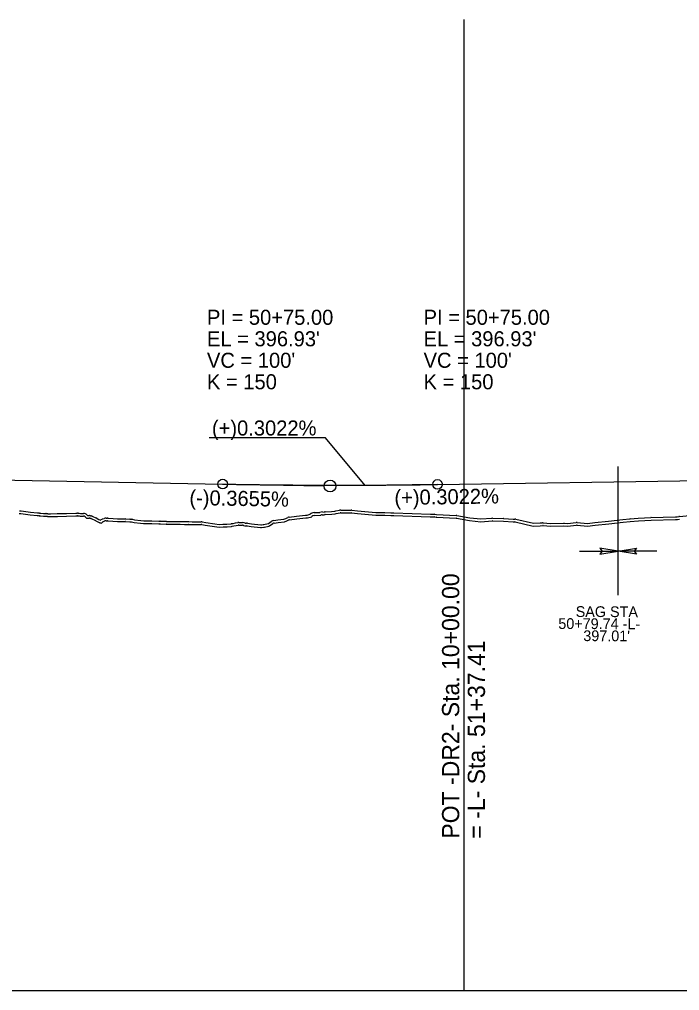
# Model space of a CAD drawing. Extents: x 1625686 to 1640492, y 1161393 to 1175642.
# Drawn here: x 1639842.2 to 1640149.4, y 1174910.8 to 1175362.5 of the extents above; entities that cross this region are included whole.
import ezdxf

# ---------------------------------------------------------------- set-up
doc = ezdxf.new("R2010")
doc.units = 0
for name, color, linetype in [('Exist Profile Cell', 7, 'Continuous'), ('Prop PFL Text', 7, 'Continuous'), ('Prop Plan Preparation Sag', 7, 'Continuous'), ('Prop Vertical Profile Curve Label', 7, 'Continuous'), ('Prop Vertical Profile Grade', 7, 'Continuous'), ('Prop Vertical Profile Grade Label', 7, 'Continuous'), ('Prop VPI Label', 7, 'Continuous'), ('Scratch_Level_1', 7, 'Continuous'), ('Scratch_Level_3', 7, 'Continuous')]:
    doc.layers.add(name, color=color, linetype=linetype)

msp = doc.modelspace()

# ---------------------------------------------------------------- linework, layer by layer
at = {"layer": 'Exist Profile Cell'}
msp.add_line((1635911.78, 1174910.79), (1640378.1, 1174910.79), dxfattribs=at)
at = {"layer": 'Prop PFL Text'}
msp.add_line((1640049.19, 1174977.9), (1640049.19, 1175146.38), dxfattribs=at)
at = {"layer": 'Prop Plan Preparation Sag'}
for p, q in [((1640120.85, 1175094.7), (1640120.85, 1175154.46)), ((1640102.85, 1175115.13), (1640120.85, 1175115.13)), ((1640138.85, 1175115.13), (1640120.85, 1175115.13))]:
    msp.add_line(p, q, dxfattribs=at)
for points in [[(1640112.29, 1175113.71), (1640120.85, 1175115.13), (1640112.29, 1175116.56), (1640113.35, 1175115.13)], [(1640129.42, 1175113.71), (1640120.85, 1175115.13), (1640129.42, 1175116.56), (1640128.35, 1175115.13)]]:
    msp.add_lwpolyline(points, close=True, dxfattribs=at)
at = {"layer": 'Prop Vertical Profile Curve Label'}
for centre in [(1639936.78, 1175146.35), (1640036.78, 1175146.19)]:
    msp.add_circle(centre, 2.25, dxfattribs=at)
at = {"layer": 'Prop Vertical Profile Grade'}
for p, q in [((1639521.78, 1175153.93), (1639936.78, 1175146.35)), ((1640036.78, 1175146.19), (1640211.78, 1175148.84))]:
    msp.add_line(p, q, dxfattribs=at)
msp.add_spline([(1639936.78, 1175146.35), (1639938.78, 1175146.31), (1639940.78, 1175146.28), (1639942.78, 1175146.25), (1639944.78, 1175146.21), (1639946.78, 1175146.18), (1639948.78, 1175146.15), (1639950.78, 1175146.13), (1639952.78, 1175146.1), (1639954.78, 1175146.08), (1639956.78, 1175146.05), (1639958.78, 1175146.03), (1639960.78, 1175146.01), (1639962.78, 1175145.99), (1639964.78, 1175145.97), (1639966.78, 1175145.95), (1639968.78, 1175145.94), (1639970.78, 1175145.92), (1639972.78, 1175145.91), (1639974.78, 1175145.9), (1639976.78, 1175145.89), (1639978.78, 1175145.88), (1639980.78, 1175145.87), (1639982.78, 1175145.86), (1639984.78, 1175145.86), (1639986.78, 1175145.85), (1639988.78, 1175145.85), (1639990.78, 1175145.85), (1639992.78, 1175145.85), (1639994.78, 1175145.85), (1639996.78, 1175145.85), (1639998.78, 1175145.86), (1640000.78, 1175145.86), (1640002.78, 1175145.87), (1640004.78, 1175145.88), (1640006.78, 1175145.89), (1640008.78, 1175145.9), (1640010.78, 1175145.91), (1640012.78, 1175145.93), (1640014.78, 1175145.94), (1640016.78, 1175145.96), (1640018.78, 1175145.97), (1640020.78, 1175145.99), (1640022.78, 1175146.01), (1640024.78, 1175146.03), (1640026.78, 1175146.06), (1640028.78, 1175146.08), (1640030.78, 1175146.11), (1640032.78, 1175146.13), (1640034.78, 1175146.16), (1640036.78, 1175146.19)], degree=3, dxfattribs=at)
at = {"layer": 'Prop Vertical Profile Grade Label'}
for p, q in [((1639984.65, 1175167.83), (1639930.45, 1175167.83)), ((1640003.16, 1175145.68), (1639984.65, 1175167.83))]:
    msp.add_line(p, q, dxfattribs=at)
at = {"layer": 'Prop VPI Label'}
for p, q in [((1639936.78, 1175146.35), (1639984.03, 1175145.49)), ((1640036.78, 1175146.19), (1639989.53, 1175145.48))]:
    msp.add_line(p, q, dxfattribs=at)
msp.add_circle((1639986.78, 1175145.44), 2.75, dxfattribs=at)
at = {"layer": 'Scratch_Level_1'}
for p, q in [((1639854.61, 1175132.65), (1639855.24, 1175132.6)), ((1639979.31, 1175133.07), (1639982.05, 1175133.15)), ((1640035.36, 1175132.31), (1640036.28, 1175132.26)), ((1640036.31, 1175132.26), (1640045.53, 1175131.7)), ((1640149.32, 1175131.33), (1640157.05, 1175132.05)), ((1639854.53, 1175131.4), (1639855.16, 1175131.36)), ((1639875.01, 1175130.44), (1639875.34, 1175130.36)), ((1639875.29, 1175131.65), (1639875.63, 1175131.58)), ((1639875.58, 1175130.28), (1639877.63, 1175129.35)), ((1639876.09, 1175131.42), (1639878.14, 1175130.49)), ((1639880.89, 1175130.13), (1639881.57, 1175130.39)), ((1639881.34, 1175128.96), (1639882.02, 1175129.23)), ((1639882.52, 1175129.31), (1639883.04, 1175129.29)), ((1639882.57, 1175130.56), (1639883.09, 1175130.54)), ((1639891.54, 1175128.99), (1639893.57, 1175128.85)), ((1639891.62, 1175130.24), (1639893.65, 1175130.1)), ((1639893.65, 1175128.84), (1639894.38, 1175128.74)), ((1639893.81, 1175130.08), (1639894.54, 1175129.98)), ((1639907.63, 1175127.92), (1639910.56, 1175127.79)), ((1639907.69, 1175129.17), (1639910.62, 1175129.04)), ((1639924.57, 1175128.86), (1639925.1, 1175128.86)), ((1639924.57, 1175127.61), (1639925.09, 1175127.61)), ((1639925.1, 1175127.61), (1639926.84, 1175127.6)), ((1639925.11, 1175128.86), (1639926.85, 1175128.85)), ((1639941.73, 1175128.1), (1639942.79, 1175128.28)), ((1639942.81, 1175128.28), (1639943.85, 1175128.45)), ((1640035.3, 1175131.06), (1640036.22, 1175131.01)), ((1640036.23, 1175131.01), (1640045.46, 1175130.46)), ((1640062.32, 1175129.27), (1640067.45, 1175129.15)), ((1640062.35, 1175130.52), (1640067.48, 1175130.4)), ((1640123.02, 1175129.93), (1640126.3, 1175130.25)), ((1640123.15, 1175128.69), (1640126.42, 1175129)), ((1639941.94, 1175126.87), (1639943, 1175127.04)), ((1639943, 1175127.04), (1639944.05, 1175127.21))]:
    msp.add_line(p, q, dxfattribs=at)
for points in [[(1639842.05, 1175132.72), (1639842.9, 1175132.62), (1639847.18, 1175132.13), (1639850.43, 1175131.75), (1639850.93, 1175131.7), (1639851.44, 1175131.66)], [(1639842.2, 1175133.97), (1639843.04, 1175133.87), (1639847.33, 1175133.37), (1639850.56, 1175132.99), (1639851.04, 1175132.94), (1639851.55, 1175132.9)], [(1639851.68, 1175132.89), (1639852.18, 1175132.82), (1639853.44, 1175132.67), (1639853.89, 1175132.66), (1639854.47, 1175132.65)], [(1639855.37, 1175132.59), (1639855.97, 1175132.52), (1639856.6, 1175132.5), (1639859.83, 1175132.6), (1639864.11, 1175132.73), (1639868.4, 1175132.86), (1639869.2, 1175132.89)], [(1639869.59, 1175132.87), (1639870.07, 1175132.81), (1639870.55, 1175132.75), (1639872.01, 1175132.7)], [(1639873.65, 1175132.01), (1639873.95, 1175131.73), (1639874.74, 1175131.72)], [(1639967.78, 1175130.99), (1639971.09, 1175131.37), (1639975.38, 1175131.85), (1639976.1, 1175131.94), (1639977.57, 1175132.3)], [(1639979.35, 1175131.82), (1639982.38, 1175131.91), (1639982.43, 1175131.94)], [(1639983.14, 1175132.13), (1639984.09, 1175132.1), (1639984.31, 1175132.14)], [(1639983.18, 1175133.38), (1639983.99, 1175133.35), (1639984.07, 1175133.37)], [(1639984.45, 1175133.41), (1639987.46, 1175133.54), (1639989, 1175133.78), (1639989.45, 1175133.86), (1639991.2, 1175134.21)], [(1639984.5, 1175132.16), (1639987.58, 1175132.3), (1639989.2, 1175132.55), (1639989.67, 1175132.63), (1639991.44, 1175132.98)], [(1639991.72, 1175133.01), (1639993.44, 1175132.97), (1639996.56, 1175133.02)], [(1639991.75, 1175134.26), (1639993.44, 1175134.22), (1639996.53, 1175134.27)], [(1639996.71, 1175133.02), (1639999.47, 1175132.73), (1640008, 1175131.88), (1640009.53, 1175131.86), (1640012.29, 1175131.84)], [(1639996.84, 1175134.26), (1639999.59, 1175133.97), (1640008.07, 1175133.13), (1640009.54, 1175133.11), (1640012.3, 1175133.09)], [(1640012.31, 1175131.84), (1640015.08, 1175131.79), (1640016.38, 1175131.77)], [(1640012.33, 1175133.09), (1640015.1, 1175133.04), (1640016.4, 1175133.02)], [(1640016.41, 1175131.77), (1640033.42, 1175131.08), (1640035.26, 1175131.06)], [(1640016.46, 1175133.02), (1640033.45, 1175132.33), (1640035.27, 1175132.31)], [(1639851.51, 1175131.65), (1639852.02, 1175131.58), (1639853.35, 1175131.42), (1639853.87, 1175131.41), (1639854.46, 1175131.4)], [(1639855.22, 1175131.35), (1639855.87, 1175131.27), (1639856.6, 1175131.25), (1639859.86, 1175131.35), (1639864.15, 1175131.48), (1639868.44, 1175131.61), (1639869.24, 1175131.64)], [(1639869.43, 1175131.63), (1639869.93, 1175131.57), (1639870.46, 1175131.51), (1639871.96, 1175131.45)], [(1639872.79, 1175131.11), (1639873.44, 1175130.48), (1639874.73, 1175130.47)], [(1639877.73, 1175129.3), (1639878.65, 1175128.78), (1639879.7, 1175128.41)], [(1639878.34, 1175130.39), (1639879.17, 1175129.92), (1639880.06, 1175129.6), (1639880.13, 1175129.66)], [(1639879.81, 1175128.36), (1639880.25, 1175128.16), (1639880.56, 1175128.37), (1639880.96, 1175128.73)], [(1639883.19, 1175129.27), (1639883.46, 1175129.23), (1639885.71, 1175129.09), (1639887.78, 1175128.95), (1639889.9, 1175128.98), (1639891.43, 1175129)], [(1639883.39, 1175130.51), (1639883.6, 1175130.47), (1639885.79, 1175130.33), (1639887.81, 1175130.2), (1639889.88, 1175130.23), (1639891.42, 1175130.25)], [(1639894.43, 1175128.74), (1639895.6, 1175128.53), (1639898.61, 1175128.23), (1639900.02, 1175128.09)], [(1639894.66, 1175129.97), (1639895.77, 1175129.76), (1639898.74, 1175129.47), (1639900.14, 1175129.33)], [(1639900.02, 1175128.09), (1639900.81, 1175128), (1639902.78, 1175128), (1639903.83, 1175128)], [(1639900.16, 1175129.33), (1639900.88, 1175129.25), (1639902.78, 1175129.25), (1639903.83, 1175129.25)], [(1639903.86, 1175128), (1639907.07, 1175127.92), (1639907.57, 1175127.92)], [(1639903.89, 1175129.25), (1639907.08, 1175129.17), (1639907.56, 1175129.17)], [(1639910.58, 1175127.79), (1639911.57, 1175127.73), (1639913.6, 1175127.69), (1639914.94, 1175127.69)], [(1639910.66, 1175129.03), (1639911.62, 1175128.98), (1639913.61, 1175128.94), (1639914.94, 1175128.94)], [(1639914.96, 1175127.69), (1639915.66, 1175127.67), (1639917.05, 1175127.65), (1639919.05, 1175127.63), (1639919.93, 1175127.63), (1639920.96, 1175127.63)], [(1639914.98, 1175128.94), (1639915.68, 1175128.92), (1639917.07, 1175128.9), (1639919.06, 1175128.88), (1639919.94, 1175128.88), (1639920.97, 1175128.88)], [(1639920.97, 1175127.63), (1639922.63, 1175127.61), (1639924.21, 1175127.61), (1639924.57, 1175127.61)], [(1639920.98, 1175128.88), (1639922.63, 1175128.86), (1639924.21, 1175128.86), (1639924.57, 1175128.86)], [(1639927.03, 1175127.58), (1639928.7, 1175127.31), (1639932.99, 1175126.62), (1639935.12, 1175126.28), (1639936.99, 1175126.4), (1639938.89, 1175126.53), (1639940.89, 1175126.69), (1639941.15, 1175126.73), (1639941.93, 1175126.87)], [(1639927.23, 1175128.81), (1639928.9, 1175128.54), (1639933.18, 1175127.85), (1639935.17, 1175127.54), (1639936.91, 1175127.65), (1639938.8, 1175127.78), (1639940.73, 1175127.93), (1639940.94, 1175127.96), (1639941.71, 1175128.1)], [(1639944.26, 1175128.48), (1639945.67, 1175128.47), (1639946.09, 1175128.46)], [(1639947.03, 1175128.28), (1639947.33, 1175128.15), (1639947.9, 1175128.18)], [(1639948.35, 1175128.17), (1639950.23, 1175127.93), (1639954.49, 1175127.47), (1639954.91, 1175127.43), (1639955.66, 1175127.54), (1639955.98, 1175127.61)], [(1639956.02, 1175127.62), (1639958.01, 1175128.03), (1639958.08, 1175128.04), (1639959.36, 1175129)], [(1639956.27, 1175126.39), (1639958.26, 1175126.81), (1639958.6, 1175126.88), (1639960.11, 1175128)], [(1639960.56, 1175129.48), (1639962.5, 1175129.71), (1639965.24, 1175130.05), (1639966.13, 1175130.41), (1639967.1, 1175130.82)], [(1639960.71, 1175128.24), (1639962.65, 1175128.47), (1639965.56, 1175128.82), (1639966.61, 1175129.26), (1639967.58, 1175129.66)], [(1639967.92, 1175129.75), (1639971.23, 1175130.12), (1639975.52, 1175130.61), (1639976.32, 1175130.7), (1639978.29, 1175131.19), (1639978.34, 1175131.25)], [(1640045.58, 1175130.44), (1640051.59, 1175129.49), (1640056.96, 1175128.86), (1640062.19, 1175129.27)], [(1640045.77, 1175131.68), (1640051.76, 1175130.73), (1640056.99, 1175130.12), (1640062.09, 1175130.51)], [(1640067.51, 1175129.14), (1640071.96, 1175128.81), (1640072.73, 1175128.79)], [(1640067.6, 1175130.39), (1640072.03, 1175130.06), (1640072.76, 1175130.04)], [(1640072.98, 1175128.76), (1640081.37, 1175126.85), (1640084.56, 1175127.01), (1640085.74, 1175127.07)], [(1640073.25, 1175129.98), (1640081.48, 1175128.11), (1640084.5, 1175128.26), (1640085.68, 1175128.32)], [(1640085.96, 1175128.32), (1640089.39, 1175128.1), (1640095.52, 1175128.17)], [(1640095.72, 1175128.17), (1640097.2, 1175128.07), (1640101.36, 1175128.45)], [(1640101.7, 1175127.2), (1640106.65, 1175126.76), (1640110.11, 1175127.27)], [(1640101.81, 1175128.45), (1640106.61, 1175128.02), (1640109.93, 1175128.5)], [(1640110.05, 1175128.52), (1640116.35, 1175129.12), (1640122.96, 1175129.92)], [(1640110.17, 1175127.28), (1640116.48, 1175127.88), (1640123.12, 1175128.68)], [(1640126.42, 1175130.26), (1640130.18, 1175130.45), (1640136.07, 1175130.77)], [(1640126.48, 1175129.01), (1640130.24, 1175129.2), (1640136.14, 1175129.52)], [(1640136.13, 1175130.77), (1640147.46, 1175131.12), (1640148.28, 1175131.16), (1640149.14, 1175131.31)], [(1640136.17, 1175129.53), (1640147.51, 1175129.88), (1640148.41, 1175129.92), (1640149.35, 1175130.07)], [(1639944.25, 1175127.23), (1639945.66, 1175127.22), (1639946.08, 1175127.21)], [(1639946.55, 1175127.12), (1639947.12, 1175126.89), (1639947.97, 1175126.93)], [(1639948.2, 1175126.93), (1639950.08, 1175126.68), (1639954.36, 1175126.23), (1639954.93, 1175126.17), (1639955.88, 1175126.31), (1639956.25, 1175126.39)], [(1640085.88, 1175127.07), (1640089.36, 1175126.85), (1640095.54, 1175126.92)], [(1640095.64, 1175126.92), (1640097.21, 1175126.81), (1640101.47, 1175127.2)]]:
    msp.add_lwpolyline(points, dxfattribs=at)
for centre, radius, start, end in [((1639851.34, 1175130.41), 2.5, 82.0237, 85.1236), ((1639854.44, 1175130.15), 2.5, 86.0358, 89.2513), ((1639855.07, 1175130.11), 2.5, 83.2386, 86.0358), ((1639869.28, 1175130.39), 2.5, 82.9494, 91.8255), ((1639871.92, 1175130.21), 2.5, 46.1986, 88.0247), ((1639979.38, 1175130.57), 2.5, 91.6323, 136.4335), ((1639979.38, 1175130.57), 1.25, 91.6323, 147.0323), ((1639983.1, 1175130.88), 2.5, 88.0965, 114.7448), ((1639983.1, 1175130.88), 1.25, 88.0965, 122.2353), ((1639984.56, 1175130.92), 2.5, 92.5023, 101.2324), ((1639984.56, 1175130.92), 1.25, 92.5023, 101.2324), ((1639991.69, 1175131.76), 2.5, 88.6806, 101.2879), ((1639991.69, 1175131.76), 1.25, 88.6806, 101.2879), ((1639996.58, 1175131.77), 2.5, 84.0361, 91.0172), ((1639996.58, 1175131.77), 1.25, 84.0361, 91.0172), ((1640012.29, 1175130.59), 1.25, 88.9421, 89.6981), ((1640012.29, 1175130.59), 2.5, 88.9421, 89.6981), ((1640016.36, 1175130.52), 1.25, 87.6899, 89.0176), ((1640016.36, 1175130.52), 2.5, 87.6899, 89.0176), ((1640035.24, 1175129.81), 2.5, 87.3258, 89.272), ((1640036.16, 1175129.77), 2.5, 86.5397, 87.3258), ((1639851.34, 1175130.41), 1.25, 82.0237, 85.1236), ((1639854.44, 1175130.15), 1.25, 86.0358, 89.2513), ((1639855.07, 1175130.11), 1.25, 83.2386, 86.0358), ((1639869.28, 1175130.39), 1.25, 82.9494, 91.8255), ((1639871.92, 1175130.21), 1.25, 46.1986, 88.0247), ((1639874.72, 1175129.22), 1.25, 76.8992, 89.5618), ((1639874.72, 1175129.22), 2.5, 76.8992, 89.5618), ((1639875.06, 1175129.14), 1.25, 65.5762, 76.8992), ((1639875.06, 1175129.14), 2.5, 65.5762, 76.8992), ((1639877.11, 1175128.21), 1.25, 60.4858, 65.5762), ((1639877.11, 1175128.21), 2.5, 60.4858, 65.5762), ((1639879.28, 1175127.23), 1.25, 65.2681, 70.6033), ((1639881.8, 1175127.8), 2.5, 111.1751, 131.8923), ((1639881.8, 1175127.8), 1.25, 111.1751, 131.8923), ((1639882.47, 1175128.06), 2.5, 87.7612, 111.1751), ((1639882.47, 1175128.06), 1.25, 87.7612, 111.1751), ((1639882.99, 1175128.04), 1.25, 80.8458, 87.7612), ((1639882.99, 1175128.04), 2.5, 80.8458, 87.7612), ((1639891.45, 1175127.75), 2.5, 86.0214, 90.7088), ((1639891.45, 1175127.75), 1.25, 86.0214, 90.7088), ((1639893.48, 1175127.6), 1.25, 82.3534, 86.0214), ((1639893.48, 1175127.6), 2.5, 82.3534, 86.0214), ((1639894.21, 1175127.51), 1.25, 79.7765, 82.3534), ((1639894.21, 1175127.51), 2.5, 79.7765, 82.3534), ((1639899.89, 1175126.84), 1.25, 83.9714, 84.3453), ((1639899.89, 1175126.84), 2.5, 83.9714, 84.3453), ((1639903.83, 1175126.75), 2.5, 88.6227, 89.9328), ((1639903.83, 1175126.75), 1.25, 88.6227, 89.9328), ((1639907.58, 1175126.67), 2.5, 87.3791, 90.4952), ((1639907.58, 1175126.67), 1.25, 87.3791, 90.4952), ((1639910.5, 1175126.54), 1.25, 86.4232, 87.3791), ((1639910.5, 1175126.54), 2.5, 86.4232, 87.3791), ((1639914.94, 1175126.44), 2.5, 89.0853, 90.0115), ((1639914.94, 1175126.44), 1.25, 89.0853, 90.0115), ((1639920.96, 1175126.38), 1.25, 89.5718, 89.8079), ((1639920.96, 1175126.38), 2.5, 89.5718, 89.8079), ((1639924.57, 1175126.36), 2.5, 89.9589, 90.0146), ((1639924.57, 1175126.36), 1.25, 89.9589, 90.0146), ((1639925.09, 1175126.36), 1.25, 89.5159, 89.9589), ((1639925.09, 1175126.36), 2.5, 89.5159, 89.9589), ((1639926.83, 1175126.35), 1.25, 80.7935, 89.5159), ((1639926.83, 1175126.35), 2.5, 80.7935, 89.5159), ((1639942.14, 1175125.63), 2.5, 99.4246, 99.8362), ((1639943.2, 1175125.81), 2.5, 99.1158, 99.4246), ((1639944.25, 1175125.98), 2.5, 89.59, 99.1158), ((1639946.07, 1175125.96), 2.5, 67.6171, 89.6196), ((1639948.04, 1175125.69), 2.5, 82.7457, 93.0515), ((1639956.52, 1175125.17), 2.5, 101.6943, 102.6083), ((1639960.86, 1175127), 2.5, 96.8626, 126.7078), ((1639960.86, 1175127), 1.25, 96.8626, 126.7078), ((1639968.06, 1175128.51), 2.5, 96.458, 112.5695), ((1639968.06, 1175128.51), 1.25, 96.458, 112.5695), ((1640035.24, 1175129.81), 1.25, 87.3258, 89.272), ((1640036.16, 1175129.77), 1.25, 86.5397, 87.3258), ((1640045.38, 1175129.21), 1.25, 81.0194, 86.5397), ((1640045.38, 1175129.21), 2.5, 81.0194, 86.5397), ((1640062.29, 1175128.02), 2.5, 88.6151, 94.4483), ((1640062.29, 1175128.02), 1.25, 88.6151, 94.4483), ((1640067.42, 1175127.9), 1.25, 85.7543, 88.6151), ((1640067.42, 1175127.9), 2.5, 85.7543, 88.6151), ((1640072.7, 1175127.54), 1.25, 77.1965, 88.4813), ((1640072.7, 1175127.54), 2.5, 77.1965, 88.4813), ((1640085.8, 1175125.82), 2.5, 86.347, 92.862), ((1640095.55, 1175125.67), 2.5, 86.1136, 90.6921), ((1640101.59, 1175125.96), 2.5, 84.9033, 95.1925), ((1640110.29, 1175126.03), 2.5, 95.4484, 98.3577), ((1640110.29, 1175126.03), 1.25, 95.4484, 98.3577), ((1640123.27, 1175127.44), 2.5, 95.5387, 96.9212), ((1640123.27, 1175127.44), 1.25, 95.5387, 96.9212), ((1640126.54, 1175127.76), 2.5, 92.9123, 95.5387), ((1640126.54, 1175127.76), 1.25, 92.9123, 95.5387), ((1640136.21, 1175128.28), 2.5, 91.7677, 93.1503), ((1640136.21, 1175128.28), 1.25, 91.7677, 93.1503), ((1640149.55, 1175128.84), 2.5, 95.2937, 99.3614), ((1640149.55, 1175128.84), 1.25, 95.2937, 99.3614), ((1639942.14, 1175125.63), 1.25, 99.4246, 99.8362), ((1639943.2, 1175125.81), 1.25, 99.1158, 99.4246), ((1639944.25, 1175125.98), 1.25, 89.59, 99.1158), ((1639946.07, 1175125.96), 1.25, 67.6171, 89.6196), ((1639948.04, 1175125.69), 1.25, 82.7457, 93.0515), ((1639956.52, 1175125.17), 1.25, 101.6943, 102.6083), ((1640085.8, 1175125.82), 1.25, 86.347, 92.862), ((1640095.55, 1175125.67), 1.25, 86.1136, 90.6921), ((1640101.59, 1175125.96), 1.25, 84.9033, 95.1925)]:
    msp.add_arc(centre, radius, start, end, dxfattribs=at)
at = {"layer": 'Scratch_Level_3'}
msp.add_line((1640036.78, 1175146.19), (1640211.78, 1175148.81), dxfattribs=at)
msp.add_lwpolyline([(1635911.78, 1174910.79), (1640049.19, 1174910.79), (1640049.19, 1175362.47)], dxfattribs=at)

# ---------------------------------------------------------------- texts
at = {"layer": 'Prop PFL Text'}
for s, p in [('POT -DR2- Sta. 10+00.00', (1640046.87, 1174981.45)), ('= -L- Sta. 51+37.41', (1640058.87, 1174981.45))]:
    msp.add_text(s, height=8, rotation=90, dxfattribs=at).set_placement(p)
at = {"layer": 'Prop Plan Preparation Sag'}
for s, p in [('SAG STA', (1640101.07, 1175084.57)), ('50+79.74 -L-', (1640092.98, 1175078.99)), ("397.01'", (1640104.61, 1175073.33))]:
    msp.add_text(s, height=5, rotation=359.7547, dxfattribs=at).set_placement(p)
at = {"layer": 'Prop Vertical Profile Curve Label'}
for s, p in [("VC = 100'", (1639929.48, 1175200.44)), ("VC = 100'", (1640030.3, 1175200.44)), ('K = 150', (1639929.48, 1175190.44)), ('K = 150', (1640030.3, 1175190.44))]:
    msp.add_text(s, height=7, dxfattribs=at).set_placement(p)
at = {"layer": 'Prop Vertical Profile Grade Label'}
msp.add_text('(+)0.3022%', height=7, dxfattribs=at).set_placement((1639931.79, 1175168.94))
for s, rotation, p in [('(-)0.3655%', 358.9532, (1639921.26, 1175136.63)), ('(+)0.3022%', 0.8657, (1640016.76, 1175136.6))]:
    msp.add_text(s, height=7, rotation=rotation, dxfattribs=at).set_placement(p)
at = {"layer": 'Prop VPI Label'}
for s, p in [('PI = 50+75.00', (1639929.48, 1175220.44)), ('PI = 50+75.00', (1640030.3, 1175220.44)), ("EL = 396.93'", (1639929.48, 1175210.44)), ("EL = 396.93'", (1640030.3, 1175210.44))]:
    msp.add_text(s, height=7, dxfattribs=at).set_placement(p)

doc.saveas('drawing.dxf')
